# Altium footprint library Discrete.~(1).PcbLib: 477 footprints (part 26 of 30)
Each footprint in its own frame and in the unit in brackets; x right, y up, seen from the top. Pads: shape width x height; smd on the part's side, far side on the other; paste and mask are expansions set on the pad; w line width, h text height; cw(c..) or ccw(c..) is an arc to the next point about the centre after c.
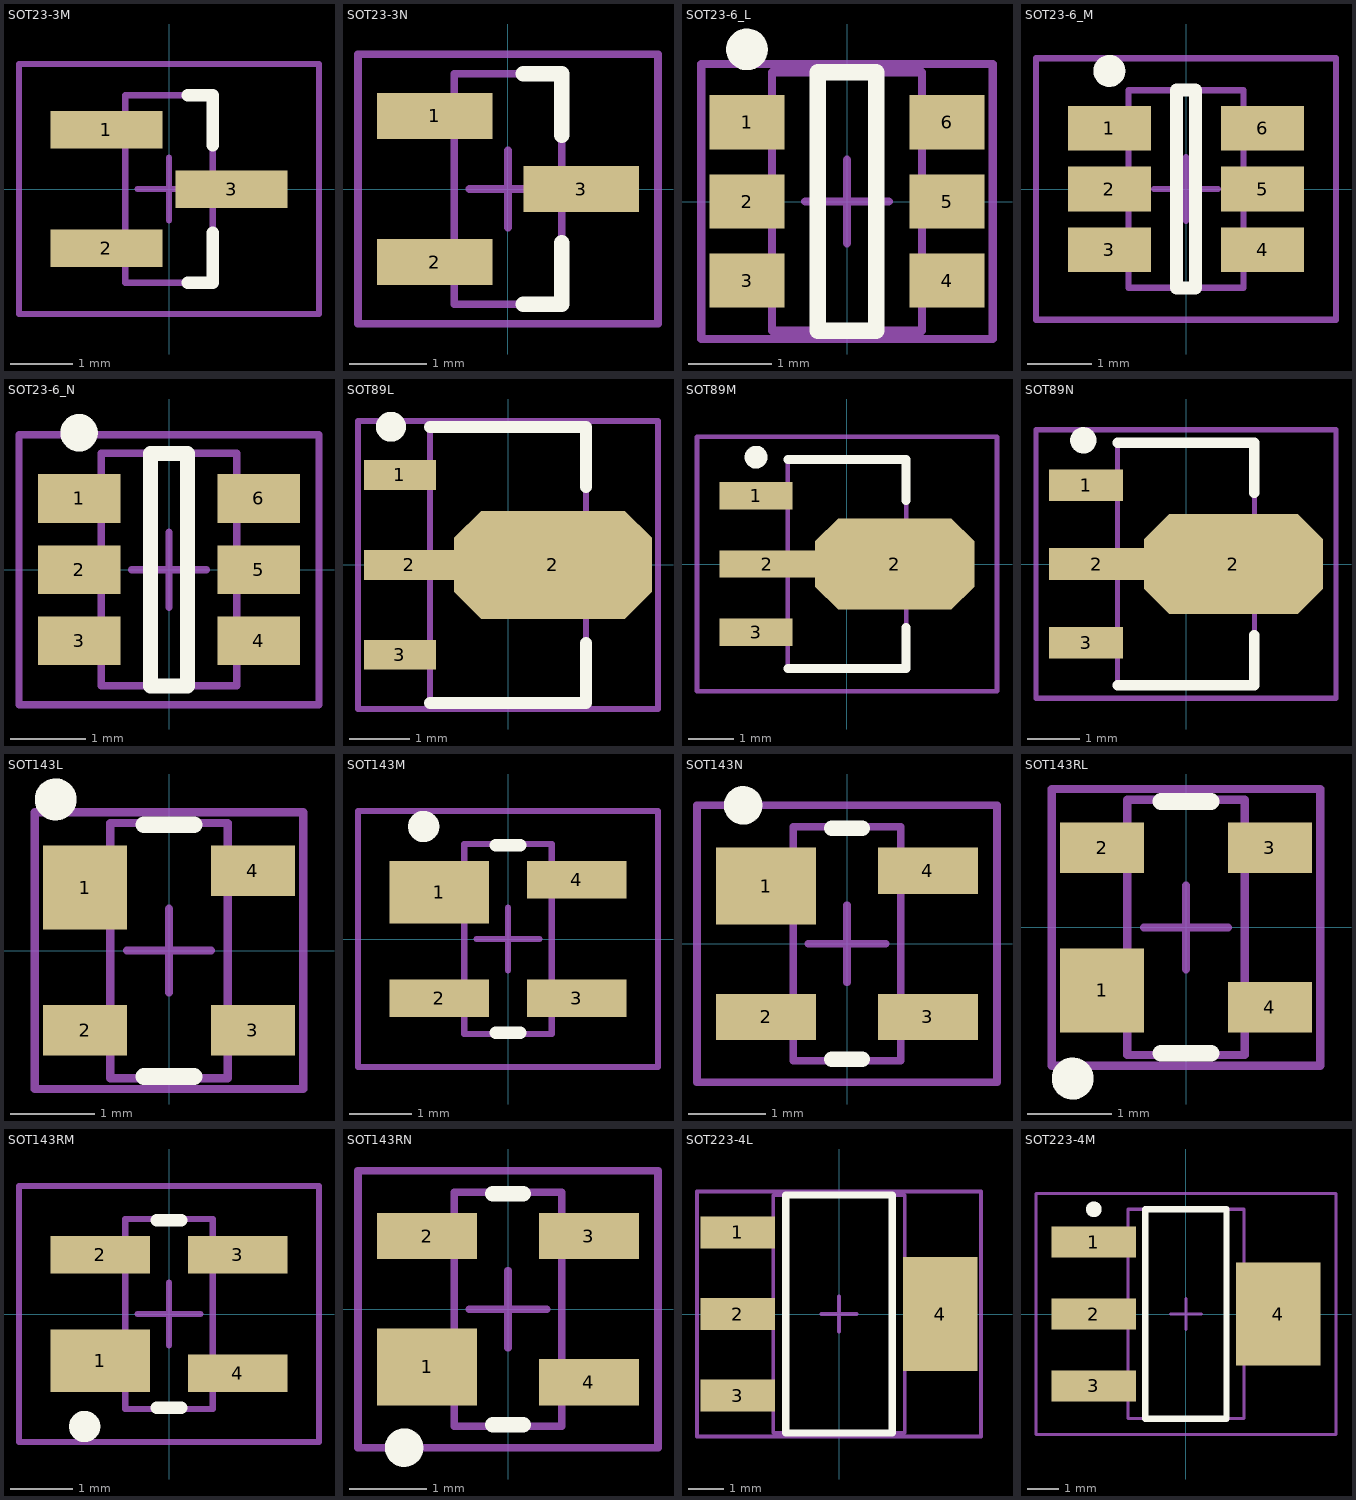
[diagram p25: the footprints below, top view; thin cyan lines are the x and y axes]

## SOT23-3M [mm] "SOT23, 3-Leads, Body 2.9x1.3mm, Pitch 0.95mm, Lead Span 2.5mm, IPC Low Density"
height 1.1
pads (3):
  rect 1.8x0.6 smd: 1(-1,0.95) 2(-1,-0.95) 3(1,0)
Top Overlay:
  lines w0.2: 0.3,-1.5 0.7,-1.5 0.7,-0.7 ; 0.3,1.5 0.7,1.5 0.7,0.7
Mechanical 13:
  lines w0.1: -0.7,-1.5 -0.7,1.5 0.7,1.5 0.7,-1.5 -0.7,-1.5
Mechanical 15:
  lines w0.1: -0.5,0 0.5,0 ; 0,-0.5 0,0.5 ; -2.4,-2 -2.4,2 2.4,2 2.4,-2 -2.4,-2
3D body "SOT23.STEP": height 1.08, standoff 0, extent -1.091,-1.5 1.549,1.5

## SOT23-3N [mm] "SOT23, 3-Leads, Body 2.9x1.3mm, Pitch 0.95mm, Lead Span 2.5mm, IPC Medium Density"
height 1.1
pads (3):
  rect 1.5x0.6 smd: 1(-0.95,0.95) 2(-0.95,-0.95) 3(0.95,0)
Top Overlay:
  lines w0.2: 0.2,-1.5 0.7,-1.5 0.7,-0.7 ; 0.2,1.5 0.7,1.5 0.7,0.7
Mechanical 13:
  lines w0.1: -0.7,-1.5 -0.7,1.5 0.7,1.5 0.7,-1.5 -0.7,-1.5
Mechanical 15:
  lines w0.1: -0.5,0 0.5,0 ; 0,-0.5 0,0.5 ; -1.95,-1.75 -1.95,1.75 1.95,1.75 1.95,-1.75 -1.95,-1.75
3D body "SOT23.STEP": height 1.08, standoff 0, extent -1.345,-1.5 1.295,1.5

## SOT23-6_L [mm] "SOT23, 6-Leads, Body 2.9x1.6mm, Pitch 0.95mm, Lead Span 2.8mm, IPC High Density"
height 1.45
pads (6):
  rect 0.9x0.65 smd: 1(-1.2,0.95) 2(-1.2,0) 3(-1.2,-0.95) 4(1.2,-0.95) 5(1.2,0) 6(1.2,0.95)
Top Overlay:
  circle w0.25: c-1.2,1.825 r0.125
  lines w0.2: -0.35,-1.55 0.35,-1.55 0.35,1.55 -0.35,1.55 -0.35,-1.55
Mechanical 13:
  lines w0.1: -0.9,-1.55 -0.9,1.55 0.9,1.55 0.9,-1.55 -0.9,-1.55
Mechanical 15:
  lines w0.1: -0.5,0 0.5,0 ; 0,-0.5 0,0.5 ; -1.75,-1.65 -1.75,1.65 1.75,1.65 1.75,-1.65 -1.75,-1.65
3D body "SOT23-6.STEP": height 1.55, standoff 0, extent -1.479,-1.5 1.53,1.5

## SOT23-6_M [mm] "SOT23, 6-Leads, Body 2.9x1.6mm, Pitch 0.95mm, Lead Span 2.8mm, IPC Low Density"
height 1.45
pads (6):
  rect 1.3x0.7 smd: 1(-1.2,0.95) 2(-1.2,0) 3(-1.2,-0.95) 4(1.2,-0.95) 5(1.2,0) 6(1.2,0.95)
Top Overlay:
  circle w0.25: c-1.2,1.85 r0.125
  lines w0.2: -0.15,-1.55 -0.15,1.55 0.15,1.55 0.15,-1.55 -0.15,-1.55
Mechanical 13:
  lines w0.1: -0.9,-1.55 0.9,-1.55 0.9,1.55 -0.9,1.55 -0.9,-1.55
Mechanical 15:
  lines w0.1: -0.5,0 0.5,0 ; 0,-0.5 0,0.5 ; -2.35,-2.05 2.35,-2.05 2.35,2.05 -2.35,2.05 -2.35,-2.05
3D body "SOT23-6.STEP": height 1.55, standoff 0, extent -1.504,-1.5 1.504,1.5

## SOT23-6_N [mm] "SOT23, 6-Leads, Body 2.9x1.6mm, Pitch 0.95mm, Lead Span 2.8mm, IPC Medium Density"
height 1.45
pads (6):
  rect 1.1x0.65 smd: 1(-1.2,0.95) 2(-1.2,0) 3(-1.2,-0.95) 4(1.2,-0.95) 5(1.2,0) 6(1.2,0.95)
Top Overlay:
  circle w0.25: c-1.2,1.825 r0.125
  lines w0.2: -0.25,-1.55 0.25,-1.55 0.25,1.55 -0.25,1.55 -0.25,-1.55
Mechanical 13:
  lines w0.1: -0.9,-1.55 -0.9,1.55 0.9,1.55 0.9,-1.55 -0.9,-1.55
Mechanical 15:
  lines w0.1: -0.5,0 0.5,0 ; 0,-0.5 0,0.5 ; -2,-1.8 -2,1.8 2,1.8 2,-1.8 -2,-1.8
3D body "SOT23-6.STEP": height 1.55, standoff 0, extent -1.479,-1.5 1.53,1.5

## SOT89L [mm] "SOT, 3-Leads, Body 4.6 x 2.6 mm, Pitch 1.5mm, IPC High Density"
height 1.8
pads (4):
  rect 1.2x0.5 smd: 1(-1.8,1.5) 3(-1.8,-1.5)
  rect 1.5x0.5 smd: 2(-1.65,0)
  oct 3.3x1.8 smd: 2(0.75,0)
Top Overlay:
  circle w0.25: c-1.95,2.3 r0.125
  lines w0.2: -1.3,-2.3 1.3,-2.3 1.3,-1.3 ; -1.3,2.3 1.3,2.3 1.3,1.3
Mechanical 13:
  lines w0.1: -1.3,-2.3 -1.3,2.3 1.3,2.3 1.3,-2.3 -1.3,-2.3
Mechanical 15:
  lines w0.1: -0.5,0 0.5,0 ; 0,-0.5 0,0.5 ; -2.5,-2.4 -2.5,2.4 2.5,2.4 2.5,-2.4 -2.5,-2.4
3D body: height 1.8, standoff 0, extent -1.3,-2.3 1.3,2.3

## SOT89M [mm] "SOT, 3-Leads, Body 4.6 x 2.6 mm, Pitch 1.5mm, IPC Low Density"
height 1.8
pads (4):
  rect 1.6x0.6 smd: 1(-2,1.5) 3(-2,-1.5)
  rect 2.1x0.6 smd: 2(-1.75,0)
  oct 3.5x2 smd: 2(1.05,0)
Top Overlay:
  circle w0.25: c-2,2.35 r0.125
  lines w0.2: -1.3,-2.3 1.3,-2.3 1.3,-1.4 ; -1.3,2.3 1.3,2.3 1.3,1.4
Mechanical 13:
  lines w0.1: -1.3,-2.3 -1.3,2.3 1.3,2.3 1.3,-2.3 -1.3,-2.3
Mechanical 15:
  lines w0.1: -0.5,0 0.5,0 ; 0,-0.5 0,0.5 ; -3.3,-2.8 -3.3,2.8 3.3,2.8 3.3,-2.8 -3.3,-2.8
3D body: height 1.8, standoff 0, extent -1.3,-2.3 1.3,2.3

## SOT89N [mm] "SOT, 3-Leads, Body 4.6 x 2.6 mm, Pitch 1.5mm, IPC Medium Density"
height 1.8
pads (4):
  rect 1.4x0.6 smd: 1(-1.9,1.5) 3(-1.9,-1.5)
  rect 1.8x0.6 smd: 2(-1.7,0)
  oct 3.4x1.9 smd: 2(0.9,0)
Top Overlay:
  circle w0.25: c-1.95,2.35 r0.125
  lines w0.2: -1.3,-2.3 1.3,-2.3 1.3,-1.35 ; -1.3,2.3 1.3,2.3 1.3,1.35
Mechanical 13:
  lines w0.1: -1.3,-2.3 -1.3,2.3 1.3,2.3 1.3,-2.3 -1.3,-2.3
Mechanical 15:
  lines w0.1: -0.5,0 0.5,0 ; 0,-0.5 0,0.5 ; -2.85,-2.55 -2.85,2.55 2.85,2.55 2.85,-2.55 -2.85,-2.55
3D body: height 1.8, standoff 0, extent -1.3,-2.3 1.3,2.3

## SOT143L [mm] "SOT143, 4-Leads, Body 2.9x1.3mm, Pitch 1.9mm, Lead Span 2.5mm, IPC High Density"
height 1.1
pads (4):
  rect 1x1 smd: 1(-1,0.75)
  rect 1x0.6 smd: 2(-1,-0.95) 3(1,-0.95) 4(1,0.95)
Top Overlay:
  circle w0.25: c-1.35,1.8 r0.125
  lines w0.2: -0.3,-1.5 0.3,-1.5 ; -0.3,1.5 0.3,1.5
Mechanical 13:
  lines w0.1: -0.7,-1.52 0.7,-1.52 0.7,1.52 -0.7,1.52 -0.7,-1.52
Mechanical 15:
  lines w0.1: -0.5,0 0.5,0 ; 0,-0.5 0,0.5 ; -1.6,-1.65 1.6,-1.65 1.6,1.65 -1.6,1.65 -1.6,-1.65
3D body: height 1.1, standoff 0, extent -0.7,-1.52 0.7,1.52

## SOT143M [mm] "SOT143, 4-Leads, Body 2.9x1.3mm, Pitch 1.9mm, Lead Span 2.5mm, IPC Low Density"
height 1.1
pads (4):
  rect 1.6x1 smd: 1(-1.1,0.75)
  rect 1.6x0.6 smd: 2(-1.1,-0.95) 3(1.1,-0.95) 4(1.1,0.95)
Top Overlay:
  circle w0.25: c-1.35,1.8 r0.125
  lines w0.2: -0.2,-1.5 0.2,-1.5 ; -0.2,1.5 0.2,1.5
Mechanical 13:
  lines w0.1: -0.7,-1.52 0.7,-1.52 0.7,1.52 -0.7,1.52 -0.7,-1.52
Mechanical 15:
  lines w0.1: -0.5,0 0.5,0 ; 0,-0.5 0,0.5 ; -2.4,-2.05 2.4,-2.05 2.4,2.05 -2.4,2.05 -2.4,-2.05
3D body: height 1.1, standoff 0, extent -0.7,-1.52 0.7,1.52

## SOT143N [mm] "SOT143, 4-Leads, Body 2.9x1.3mm, Pitch 1.9mm, Lead Span 2.5mm, IPC Medium Density"
height 1.1
pads (4):
  rect 1.3x1 smd: 1(-1.05,0.75)
  rect 1.3x0.6 smd: 2(-1.05,-0.95) 3(1.05,-0.95) 4(1.05,0.95)
Top Overlay:
  circle w0.25: c-1.35,1.8 r0.125
  lines w0.2: -0.2,-1.5 0.2,-1.5 ; -0.2,1.5 0.2,1.5
Mechanical 13:
  lines w0.1: -0.7,-1.52 -0.7,1.52 0.7,1.52 0.7,-1.52 -0.7,-1.52
Mechanical 15:
  lines w0.1: -0.5,0 0.5,0 ; 0,-0.5 0,0.5 ; -1.95,-1.8 -1.95,1.8 1.95,1.8 1.95,-1.8 -1.95,-1.8
3D body: height 1.1, standoff 0, extent -0.7,-1.52 0.7,1.52

## SOT143RL [mm] "SOT143, 4-Leads, Body 2.9x1.3mm, Pitch 1.9mm, Lead Span 2.3mm - Reverse Pinning, IPC High Density"
height 1.1
pads (4):
  rect 1x1 smd: 1(-1,-0.75)
  rect 1x0.6 smd: 2(-1,0.95) 3(1,0.95) 4(1,-0.95)
Top Overlay:
  circle w0.25: c-1.35,-1.8 r0.125
  lines w0.2: -0.3,-1.5 0.3,-1.5 ; -0.3,1.5 0.3,1.5
Mechanical 13:
  lines w0.1: -0.7,-1.52 0.7,-1.52 0.7,1.52 -0.7,1.52 -0.7,-1.52
Mechanical 15:
  lines w0.1: -0.5,0 0.5,0 ; 0,-0.5 0,0.5 ; -1.6,-1.65 1.6,-1.65 1.6,1.65 -1.6,1.65 -1.6,-1.65
3D body: height 1.1, standoff 0, extent -0.7,-1.52 0.7,1.52

## SOT143RM [mm] "SOT143, 4-Leads, Body 2.9x1.3mm, Pitch 1.9mm, Lead Span 2.3mm - Reverse Pinning, IPC Low Density"
height 1.1
pads (4):
  rect 1.6x1 smd: 1(-1.1,-0.75)
  rect 1.6x0.6 smd: 2(-1.1,0.95) 3(1.1,0.95) 4(1.1,-0.95)
Top Overlay:
  circle w0.25: c-1.35,-1.8 r0.125
  lines w0.2: -0.2,-1.5 0.2,-1.5 ; -0.2,1.5 0.2,1.5
Mechanical 13:
  lines w0.1: -0.7,-1.52 -0.7,1.52 0.7,1.52 0.7,-1.52 -0.7,-1.52
Mechanical 15:
  lines w0.1: -0.5,0 0.5,0 ; 0,-0.5 0,0.5 ; -2.4,-2.05 -2.4,2.05 2.4,2.05 2.4,-2.05 -2.4,-2.05
3D body: height 1.1, standoff 0, extent -0.7,-1.52 0.7,1.52

## SOT143RN [mm] "SOT143, 4-Leads, Body 2.9x1.3mm, Pitch 1.9mm, Lead Span 2.3mm - Reverse Pinning, IPC Medium Density"
height 1.1
pads (4):
  rect 1.3x1 smd: 1(-1.05,-0.75)
  rect 1.3x0.6 smd: 2(-1.05,0.95) 3(1.05,0.95) 4(1.05,-0.95)
Top Overlay:
  circle w0.25: c-1.35,-1.8 r0.125
  lines w0.2: -0.2,-1.5 0.2,-1.5 ; -0.2,1.5 0.2,1.5
Mechanical 13:
  lines w0.1: -0.7,-1.52 -0.7,1.52 0.7,1.52 0.7,-1.52 -0.7,-1.52
Mechanical 15:
  lines w0.1: -0.5,0 0.5,0 ; 0,-0.5 0,0.5 ; -1.95,-1.8 -1.95,1.8 1.95,1.8 1.95,-1.8 -1.95,-1.8
3D body: height 1.1, standoff 0, extent -0.7,-1.52 0.7,1.52

## SOT223-4L [mm] "SOT223/SC73, 4-Leads, Body 6.5x3.5mm, Pitch 2.3mm, Lead Span 7mm, IPC High Density"
height 1.8
pads (4):
  rect 2.1x0.9 smd: 1(-2.85,2.3) 2(-2.85,0) 3(-2.85,-2.3)
  rect 2.1x3.2 smd: 4(2.85,0)
Top Overlay:
  lines w0.2: -1.5,-3.35 -1.5,3.35 1.5,3.35 1.5,-3.35 -1.5,-3.35
Mechanical 13:
  lines w0.1: -1.85,-3.35 -1.85,3.35 1.85,3.35 1.85,-3.35 -1.85,-3.35
Mechanical 15:
  lines w0.1: -0.5,0 0.5,0 ; 0,-0.5 0,0.5 ; -4,-3.45 -4,3.45 4,3.45 4,-3.45 -4,-3.45
3D body "SOT223.STEP": height 1.74, standoff 0.09, extent -3.551,-3.275 3.449,3.225

## SOT223-4M [mm] "SOT223/SC73, 4-Leads, Body 6.5x3.5mm, Pitch 2.3mm, Lead Span 7mm, IPC Low Density"
height 1.8
pads (4):
  rect 2.7x1 smd: 1(-2.95,2.3) 2(-2.95,0) 3(-2.95,-2.3)
  rect 2.7x3.3 smd: 4(2.95,0)
Top Overlay:
  circle w0.25: c-2.95,3.35 r0.125
  lines w0.2: -1.3,-3.35 1.3,-3.35 1.3,3.35 -1.3,3.35 -1.3,-3.35
Mechanical 13:
  lines w0.1: -1.85,-3.35 1.85,-3.35 1.85,3.35 -1.85,3.35 -1.85,-3.35
Mechanical 15:
  lines w0.1: -0.5,0 0.5,0 ; 0,-0.5 0,0.5 ; -4.8,-3.85 4.8,-3.85 4.8,3.85 -4.8,3.85 -4.8,-3.85
3D body "SOT223.STEP": height 1.74, standoff 0.09, extent -3.551,-3.275 3.449,3.225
